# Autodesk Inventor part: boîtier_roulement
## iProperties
Shininess: 64.0
Length Units: 11269
Angle Units: 11279
Time Units: 11290
Mass Units: 11283
Length Display Precision: 3
Angle Display Precision: 2
Compacted: True
Part Number: boîtier_roulement
Document SubType Name: Modeling
Created: 2004-05
Material: Par défaut
Designer: David
Density: 0.0
Volumn: 0.0
Area: 0.0
PropertySet Name: Model Information
Control State: 0
Master: False
Checked Out: False
Author: David
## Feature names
1. Extrusion1
2. Extrusion2
3. Congé1 [Fillet]
4. Perçage1 [Hole]
5. Perçage2 [Hole]
